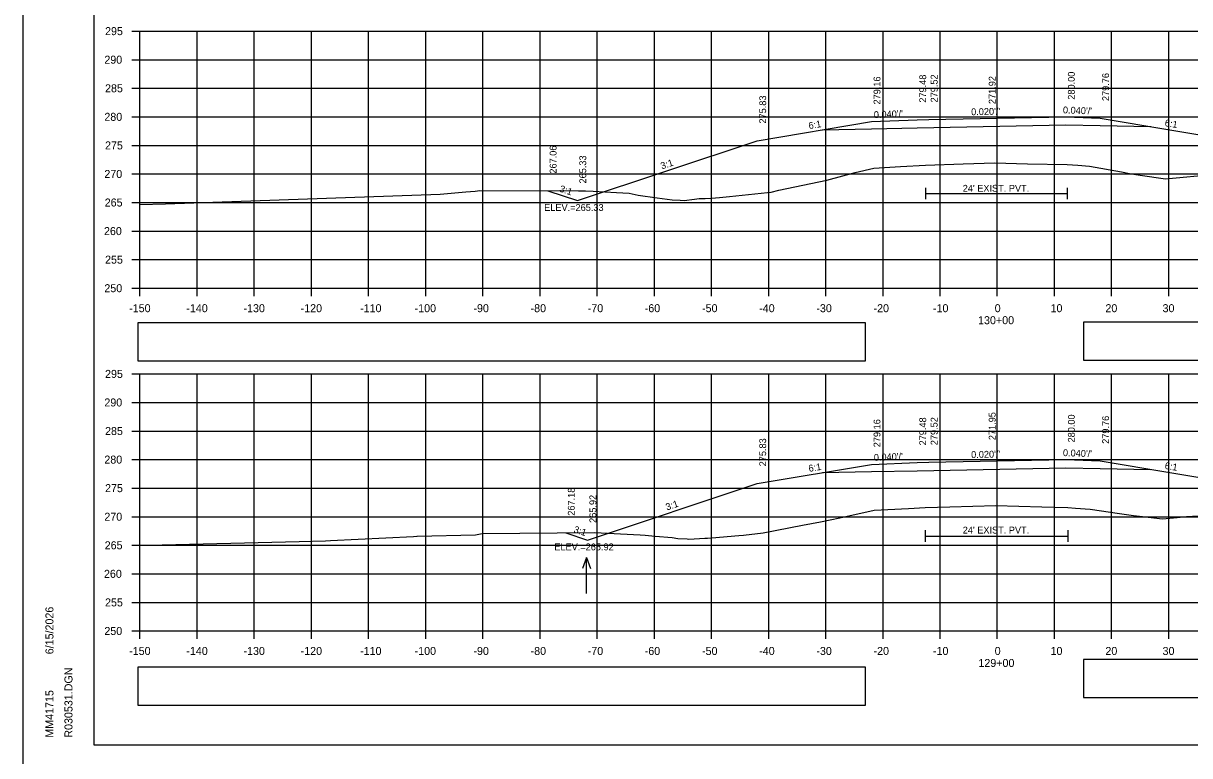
# Model space of a CAD drawing. Extents: x 285 to 4233, y -659 to 3710.
# Drawn here: x 368.9 to 572.9, y 1685 to 1813.2 of the extents above; entities that cross this region are included whole.
import ezdxf

# ---------------------------------------------------------------- set-up
doc = ezdxf.new("R2010")
doc.units = 0
for name, color, linetype in [('R_Alt Surface', 7, 'Continuous'), ('R_Axis', 7, 'Continuous'), ('R_Axis Annot', 7, 'Continuous'), ('R_Border', 7, 'Continuous'), ('R_Exist Surface', 7, 'Continuous'), ('R_Fin Surface', 7, 'Continuous'), ('R_Grid', 7, 'Continuous'), ('R_No Plot', 7, 'Continuous'), ('R_Proposed Const Limits', 7, 'Continuous'), ('R_Water', 7, 'Continuous'), ('R_Water Annot', 7, 'Continuous'), ('R_Xsect Elev', 7, 'Continuous'), ('R_Xsect Slope', 7, 'Continuous')]:
    doc.layers.add(name, color=color, linetype=linetype)

msp = doc.modelspace()

# ---------------------------------------------------------------- linework, layer by layer
at = {"layer": 'R_Alt Surface'}
for points in [[(508.71, 1794.59), (517.28, 1794.76), (525.28, 1794.92), (551.28, 1795.44), (551.28, 1795.44), (557.28, 1795.32), (566.12, 1795.14)], [(526.73, 1784.42), (526.73, 1782.42)], [(551.52, 1784.42), (551.52, 1782.42)], [(526.73, 1783.42), (551.52, 1783.42)], [(508.71, 1734.59), (517.28, 1734.76), (525.28, 1734.92), (551.28, 1735.44), (551.28, 1735.44), (557.28, 1735.32), (566.12, 1735.14)], [(526.66, 1724.48), (526.66, 1722.48)], [(551.6, 1724.48), (551.6, 1722.48)], [(526.66, 1723.48), (551.6, 1723.48)]]:
    msp.add_lwpolyline(points, dxfattribs=at)
at = {"layer": 'R_Axis'}
for p, q in [((387.88, 1811.86), (389.28, 1811.86)), ((389.28, 1766.86), (389.28, 1811.86)), ((387.88, 1806.86), (389.28, 1806.86)), ((387.88, 1801.86), (389.28, 1801.86)), ((387.88, 1796.86), (389.28, 1796.86)), ((387.88, 1791.86), (389.28, 1791.86)), ((387.88, 1786.86), (389.28, 1786.86)), ((387.88, 1781.86), (389.28, 1781.86)), ((387.88, 1776.86), (389.28, 1776.86)), ((387.88, 1771.86), (389.28, 1771.86)), ((387.88, 1766.86), (389.28, 1766.86)), ((389.28, 1766.86), (689.28, 1766.86)), ((389.28, 1765.46), (389.28, 1766.86)), ((399.28, 1765.46), (399.28, 1766.86)), ((409.28, 1765.46), (409.28, 1766.86)), ((419.28, 1765.46), (419.28, 1766.86)), ((429.28, 1765.46), (429.28, 1766.86)), ((439.28, 1765.46), (439.28, 1766.86)), ((449.28, 1765.46), (449.28, 1766.86)), ((459.28, 1765.46), (459.28, 1766.86)), ((469.28, 1765.46), (469.28, 1766.86)), ((479.28, 1765.46), (479.28, 1766.86)), ((489.28, 1765.46), (489.28, 1766.86)), ((499.28, 1765.46), (499.28, 1766.86)), ((509.28, 1765.46), (509.28, 1766.86)), ((519.28, 1765.46), (519.28, 1766.86)), ((529.28, 1765.46), (529.28, 1766.86)), ((539.28, 1765.46), (539.28, 1766.86)), ((549.28, 1765.46), (549.28, 1766.86)), ((559.28, 1765.46), (559.28, 1766.86)), ((569.28, 1765.46), (569.28, 1766.86)), ((387.88, 1751.86), (389.28, 1751.86)), ((389.28, 1706.86), (389.28, 1751.86)), ((387.88, 1746.86), (389.28, 1746.86)), ((387.88, 1741.86), (389.28, 1741.86)), ((387.88, 1736.86), (389.28, 1736.86)), ((387.88, 1731.86), (389.28, 1731.86)), ((387.88, 1726.86), (389.28, 1726.86)), ((387.88, 1721.86), (389.28, 1721.86)), ((387.88, 1716.86), (389.28, 1716.86)), ((387.88, 1711.86), (389.28, 1711.86)), ((387.88, 1706.86), (389.28, 1706.86)), ((389.28, 1706.86), (689.28, 1706.86)), ((389.28, 1705.46), (389.28, 1706.86)), ((399.28, 1705.46), (399.28, 1706.86)), ((409.28, 1705.46), (409.28, 1706.86)), ((419.28, 1705.46), (419.28, 1706.86)), ((429.28, 1705.46), (429.28, 1706.86)), ((439.28, 1705.46), (439.28, 1706.86)), ((449.28, 1705.46), (449.28, 1706.86)), ((459.28, 1705.46), (459.28, 1706.86)), ((469.28, 1705.46), (469.28, 1706.86)), ((479.28, 1705.46), (479.28, 1706.86)), ((489.28, 1705.46), (489.28, 1706.86)), ((499.28, 1705.46), (499.28, 1706.86)), ((509.28, 1705.46), (509.28, 1706.86)), ((519.28, 1705.46), (519.28, 1706.86)), ((529.28, 1705.46), (529.28, 1706.86)), ((539.28, 1705.46), (539.28, 1706.86)), ((549.28, 1705.46), (549.28, 1706.86)), ((559.28, 1705.46), (559.28, 1706.86)), ((569.28, 1705.46), (569.28, 1706.86))]:
    msp.add_line(p, q, dxfattribs=at)
at = {"layer": 'R_Axis Annot'}
for points in [[(388.91, 1754.13), (516.24, 1754.13), (516.24, 1760.78), (388.91, 1760.78)], [(554.36, 1754.24), (694.72, 1754.24), (694.72, 1760.89), (554.36, 1760.89)], [(388.91, 1693.89), (516.24, 1693.89), (516.24, 1700.54), (388.91, 1700.54)], [(554.36, 1695.2), (694.72, 1695.2), (694.72, 1701.85), (554.36, 1701.85)]]:
    msp.add_lwpolyline(points, close=True, dxfattribs=at)
at = {"layer": 'R_Border'}
for p, q in [((381.28, 1686.86), (381.28, 1892.32)), ((381.28, 1686.86), (381.28, 1686.86)), ((697.46, 1686.86), (381.28, 1686.86))]:
    msp.add_line(p, q, dxfattribs=at)
at = {"layer": 'R_Exist Surface'}
for points in [[(389.28, 1781.52), (393.73, 1781.62), (441.83, 1783.33), (446.31, 1783.74), (447.95, 1783.87), (448.76, 1783.97), (466.02, 1783.89), (467.25, 1783.88), (468.56, 1783.82), (472.65, 1783.63), (474.86, 1783.52), (476.43, 1783.16), (479.76, 1782.68), (482.41, 1782.35), (483.8, 1782.28), (484.51, 1782.24), (486.29, 1782.46), (487.12, 1782.56), (488.14, 1782.58), (489.3, 1782.61), (490.65, 1782.75), (492.42, 1782.93), (499.06, 1783.63), (499.73, 1783.7), (501.05, 1784), (509.48, 1785.76), (514.38, 1787.1), (517.67, 1787.9), (522.34, 1788.17), (526.73, 1788.42), (533.33, 1788.62), (538.82, 1788.79), (544.53, 1788.66), (551.52, 1788.49), (553.35, 1788.38), (555.43, 1788.24), (561.02, 1787.21), (562.39, 1786.95), (564.25, 1786.67), (568.68, 1786), (577.42, 1786.8)], [(389.28, 1721.85), (390.79, 1721.89), (417.14, 1722.53), (421.74, 1722.65), (422.62, 1722.68), (437.15, 1723.41), (437.71, 1723.44), (437.79, 1723.44), (447.96, 1723.68), (449.15, 1723.93), (449.16, 1723.93), (449.23, 1723.93), (468.83, 1724.08), (476.77, 1723.68), (477.68, 1723.63), (479.4, 1723.45), (482.42, 1723.22), (483.38, 1723.06), (485.04, 1722.97), (485.31, 1722.95), (488.13, 1723.1), (488.59, 1723.12), (489.31, 1723.18), (494.03, 1723.55), (494.87, 1723.65), (498.32, 1724.05), (505.22, 1725.38), (508.33, 1725.94), (511.7, 1726.68), (517.76, 1727.98), (523.76, 1728.32), (526.66, 1728.48), (530.96, 1728.6), (539.03, 1728.82), (547.04, 1728.6), (551.6, 1728.48), (552.98, 1728.38), (555.51, 1728.19), (560.68, 1727.45), (563.11, 1727.1), (564.66, 1726.91), (568.18, 1726.47), (570.75, 1726.71), (572.35, 1726.87), (577.49, 1727.19)]]:
    msp.add_lwpolyline(points, dxfattribs=at)
at = {"layer": 'R_Fin Surface'}
for points in [[(460.61, 1783.92), (465.8, 1782.19), (497.28, 1792.68), (517.28, 1796.02), (525.28, 1796.34), (527.28, 1796.38), (551.28, 1796.86), (557.28, 1796.62), (581.28, 1792.62), (609.44, 1783.23), (630.37, 1790.21)], [(463.79, 1724.04), (467.57, 1722.78), (497.28, 1732.68), (517.28, 1736.02), (525.28, 1736.34), (527.28, 1736.38), (551.28, 1736.86), (557.28, 1736.62), (581.28, 1732.62), (602.16, 1725.66), (615.28, 1730.03)]]:
    msp.add_lwpolyline(points, dxfattribs=at)
at = {"layer": 'R_Grid'}
for p, q in [((389.28, 1811.86), (689.28, 1811.86)), ((389.28, 1766.86), (389.28, 1811.86)), ((399.28, 1766.86), (399.28, 1811.86)), ((409.28, 1766.86), (409.28, 1811.86)), ((419.28, 1766.86), (419.28, 1811.86)), ((429.28, 1766.86), (429.28, 1811.86)), ((439.28, 1766.86), (439.28, 1811.86)), ((449.28, 1766.86), (449.28, 1811.86)), ((459.28, 1766.86), (459.28, 1811.86)), ((469.28, 1766.86), (469.28, 1811.86)), ((479.28, 1766.86), (479.28, 1811.86)), ((489.28, 1766.86), (489.28, 1811.86)), ((499.28, 1766.86), (499.28, 1811.86)), ((509.28, 1766.86), (509.28, 1811.86)), ((519.28, 1766.86), (519.28, 1811.86)), ((529.28, 1766.86), (529.28, 1811.86)), ((539.28, 1766.86), (539.28, 1811.86)), ((549.28, 1766.86), (549.28, 1811.86)), ((559.28, 1766.86), (559.28, 1811.86)), ((569.28, 1766.86), (569.28, 1811.86)), ((389.28, 1806.86), (689.28, 1806.86)), ((389.28, 1801.86), (689.28, 1801.86)), ((389.28, 1796.86), (689.28, 1796.86)), ((389.28, 1791.86), (689.28, 1791.86)), ((389.28, 1786.86), (689.28, 1786.86)), ((389.28, 1781.86), (689.28, 1781.86)), ((389.28, 1776.86), (689.28, 1776.86)), ((389.28, 1771.86), (689.28, 1771.86)), ((389.28, 1766.86), (689.28, 1766.86)), ((389.28, 1751.86), (689.28, 1751.86)), ((389.28, 1706.86), (389.28, 1751.86)), ((399.28, 1706.86), (399.28, 1751.86)), ((409.28, 1706.86), (409.28, 1751.86)), ((419.28, 1706.86), (419.28, 1751.86)), ((429.28, 1706.86), (429.28, 1751.86)), ((439.28, 1706.86), (439.28, 1751.86)), ((449.28, 1706.86), (449.28, 1751.86)), ((459.28, 1706.86), (459.28, 1751.86)), ((469.28, 1706.86), (469.28, 1751.86)), ((479.28, 1706.86), (479.28, 1751.86)), ((489.28, 1706.86), (489.28, 1751.86)), ((499.28, 1706.86), (499.28, 1751.86)), ((509.28, 1706.86), (509.28, 1751.86)), ((519.28, 1706.86), (519.28, 1751.86)), ((529.28, 1706.86), (529.28, 1751.86)), ((539.28, 1706.86), (539.28, 1751.86)), ((549.28, 1706.86), (549.28, 1751.86)), ((559.28, 1706.86), (559.28, 1751.86)), ((569.28, 1706.86), (569.28, 1751.86)), ((389.28, 1746.86), (689.28, 1746.86)), ((389.28, 1741.86), (689.28, 1741.86)), ((389.28, 1736.86), (689.28, 1736.86)), ((389.28, 1731.86), (689.28, 1731.86)), ((389.28, 1726.86), (689.28, 1726.86)), ((389.28, 1721.86), (689.28, 1721.86)), ((389.28, 1716.86), (689.28, 1716.86)), ((389.28, 1711.86), (689.28, 1711.86)), ((389.28, 1706.86), (689.28, 1706.86))]:
    msp.add_line(p, q, dxfattribs=at)
at = {"layer": 'R_No Plot'}
for points in [[(368.87, 1896.21), (702.21, 1896.21), (702.21, 1682.87), (368.87, 1682.87)], [(615.2, 1892.32), (634.82, 1892.32), (634.82, 1882.44), (650.93, 1882.44), (674.13, 1882.44), (674.25, 1854.28), (697.46, 1854.28), (697.46, 1686.86), (381.28, 1686.86), (381.28, 1892.32)]]:
    msp.add_lwpolyline(points, close=True, dxfattribs=at)
at = {"layer": 'R_Proposed Const Limits'}
for points in [[(527.28, 1796.38), (527.28, 1796.38), (527.28, 1796.38)], [(551.28, 1796.86), (551.28, 1796.86), (551.28, 1796.86)], [(551.28, 1736.86), (551.28, 1736.86), (551.28, 1736.86)], [(527.28, 1736.38), (527.28, 1736.38), (527.28, 1736.38)]]:
    msp.add_lwpolyline(points, dxfattribs=at)
at = {"layer": 'R_Water Annot'}
for p, q in [((467.42, 1719.72), (466.72, 1717.8)), ((467.42, 1713.44), (467.42, 1719.72)), ((467.42, 1719.72), (468.12, 1717.8))]:
    msp.add_line(p, q, dxfattribs=at)
at = {"layer": 'R_Xsect Elev'}
for p, q in [((539.28, 1788.78), (539.28, 1804.31)), ((539.28, 1728.81), (539.28, 1745.61))]:
    msp.add_line(p, q, dxfattribs=at)

# ---------------------------------------------------------------- texts
at = {"layer": 'R_Axis Annot'}
for s, p in [('295', (383.17, 1811.16)), ('290', (383.05, 1806.16)), ('285', (383.17, 1801.16)), ('280', (383.05, 1796.16)), ('275', (383.17, 1791.16)), ('270', (383.05, 1786.16)), ('265', (383.11, 1781.16)), ('260', (382.98, 1776.16)), ('255', (383.17, 1771.16)), ('250', (383.05, 1766.16)), ('-150', (387.39, 1762.66)), ('-140', (397.39, 1762.66)), ('-130', (407.39, 1762.66)), ('-120', (417.39, 1762.66)), ('-110', (427.79, 1762.66)), ('-100', (437.33, 1762.66)), ('-90', (447.62, 1762.66)), ('-80', (457.62, 1762.66)), ('-70', (467.62, 1762.66)), ('-60', (477.59, 1762.66)), ('-50', (487.62, 1762.66)), ('-40', (497.62, 1762.66)), ('-30', (507.62, 1762.66)), ('-20', (517.62, 1762.66)), ('-10', (528.02, 1762.66)), ('0', (538.82, 1762.66)), ('10', (548.59, 1762.66)), ('20', (558.19, 1762.66)), ('30', (568.19, 1762.66)), ('130+00', (535.91, 1760.56)), ('295', (383.17, 1751.16)), ('290', (383.05, 1746.16)), ('285', (383.17, 1741.16)), ('280', (383.05, 1736.16)), ('275', (383.17, 1731.16)), ('270', (383.05, 1726.16)), ('265', (383.11, 1721.16)), ('260', (382.98, 1716.16)), ('255', (383.17, 1711.16)), ('250', (383.05, 1706.16)), ('-150', (387.39, 1702.66)), ('-140', (397.39, 1702.66)), ('-130', (407.39, 1702.66)), ('-120', (417.39, 1702.66)), ('-110', (427.79, 1702.66)), ('-100', (437.33, 1702.66)), ('-90', (447.62, 1702.66)), ('-80', (457.62, 1702.66)), ('-70', (467.62, 1702.66)), ('-60', (477.59, 1702.66)), ('-50', (487.62, 1702.66)), ('-40', (497.62, 1702.66)), ('-30', (507.62, 1702.66)), ('-20', (517.62, 1702.66)), ('-10', (528.02, 1702.66)), ('0', (538.82, 1702.66)), ('10', (548.59, 1702.66)), ('20', (558.19, 1702.66)), ('30', (568.19, 1702.66)), ('129+00', (535.97, 1700.56))]:
    msp.add_text(s, height=1.4, dxfattribs=at).set_placement(p)
at = {"layer": 'R_Border'}
for s, p in [('6/15/2026', (374.14, 1702.78)), ('R030531.DGN', (377.47, 1688.18)), ('MM41715', (374.14, 1688.18))]:
    msp.add_text(s, height=1.4, rotation=90, dxfattribs=at).set_placement(p)
at = {"layer": 'R_Water'}
for p in [(533.23, 1783.75), (533.23, 1723.92)]:
    msp.add_text("24' EXIST. PVT.", height=1.2, dxfattribs=at).set_placement(p)
at = {"layer": 'R_Xsect Elev'}
for s, p in [('279.48', (526.83, 1799.34)), ('279.52', (528.83, 1799.38)), ('271.92', (538.98, 1799.09)), ('280.00', (552.83, 1799.86)), ('279.76', (558.83, 1799.62)), ('279.16', (518.83, 1799.02)), ('275.83', (498.83, 1795.68)), ('267.06', (462.16, 1786.92)), ('265.33', (467.35, 1785.19)), ('271.95', (538.98, 1740.26)), ('279.16', (518.83, 1739.02)), ('279.48', (526.83, 1739.34)), ('279.52', (528.83, 1739.38)), ('280.00', (552.83, 1739.86)), ('279.76', (558.83, 1739.62)), ('275.83', (498.83, 1735.68)), ('267.18', (465.34, 1727.04)), ('265.92', (469.12, 1725.78))]:
    msp.add_text(s, height=1.2, rotation=90, dxfattribs=at).set_placement(p)
for s, p in [('ELEV.=265.33', (460, 1780.39)), ('ELEV.=265.92', (461.77, 1720.98))]:
    msp.add_text(s, height=1.2, dxfattribs=at).set_placement(p)
at = {"layer": 'R_Xsect Slope'}
for s, rotation, p in [("0.040'/'", 2.2906, (517.7, 1796.63)), ("0.020'/'", 1.1458, (534.71, 1797.13)), ("0.040'/'", 357.7094, (550.74, 1797.48)), ('6:1', 9.4623, (506.35, 1794.7)), ('6:1', 350.5377, (568.51, 1795.25)), ('3:1', 18.4349, (480.59, 1787.65)), ('3:1', 341.5651, (462.57, 1783.79)), ("0.040'/'", 357.7094, (550.74, 1737.48)), ("0.040'/'", 2.2906, (517.7, 1736.63)), ("0.020'/'", 1.1458, (534.71, 1737.13)), ('6:1', 9.4623, (506.35, 1734.7)), ('6:1', 350.5377, (568.51, 1735.25)), ('3:1', 18.4349, (481.48, 1727.94)), ('3:1', 341.5651, (465.05, 1724.15))]:
    msp.add_text(s, height=1.2, rotation=rotation, dxfattribs=at).set_placement(p)

doc.saveas('drawing.dxf')
